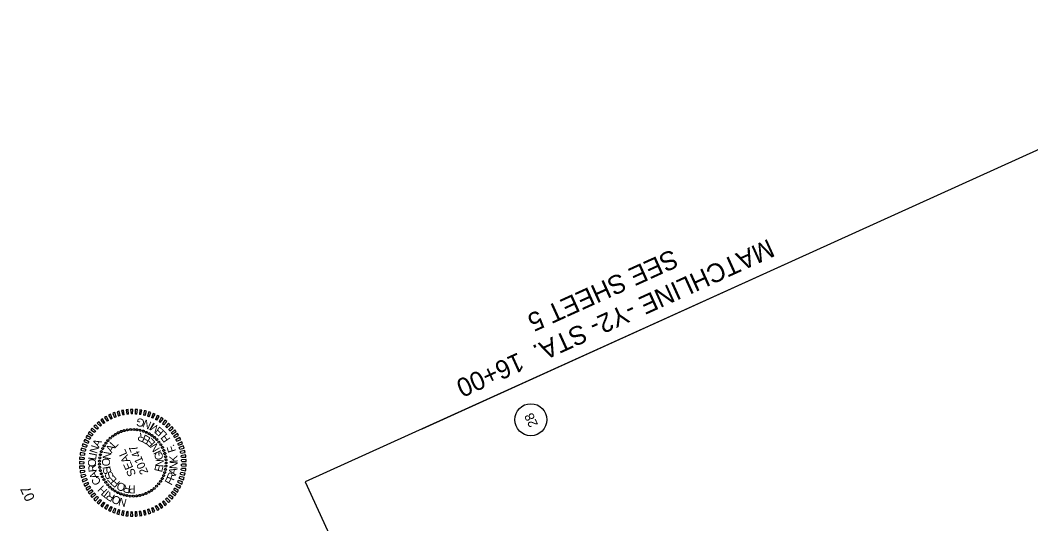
# Model space of a CAD drawing. Extents: x 2048005 to 2049520, y 757591 to 759287.
# Drawn here: x 2048005 to 2048763, y 758824 to 759201 of the extents above; entities that cross this region are included whole.
import ezdxf

# ---------------------------------------------------------------- set-up
doc = ezdxf.new("R2010")
doc.units = 0
for name, color, linetype in [('Default', 7, 'Continuous'), ('Matchline', 7, 'Continuous'), ('Matchline Text', 7, 'Continuous'), ('Sheet Clip Boundary CELL', 7, 'Continuous'), ('Sheet Data Field CELL', 7, 'Continuous'), ('Sheet PE Seal Cell', 7, 'Continuous')]:
    doc.layers.add(name, color=color, linetype=linetype)

msp = doc.modelspace()

# ---------------------------------------------------------------- linework, layer by layer
at = {"layer": 'Default'}
msp.add_line((2048387.91, 758901.83), (2048387.91, 758901.83), dxfattribs=at)
msp.add_circle((2048387.91, 758901.83), 12, dxfattribs=at)
at = {"layer": 'Matchline'}
msp.add_line((2048306.53, 758894.91), (2048583.6, 759020.66), dxfattribs=at)
at = {"layer": 'Sheet Clip Boundary CELL'}
msp.add_lwpolyline([(2048565.47, 757590.62), (2049520.08, 758027.9), (2048982.56, 759201.34), (2048218.78, 758855.25), (2048270.17, 758743.08), (2048168.29, 758696.41), (2048234.11, 758552.71), (2048143.72, 758511.31)], close=True, dxfattribs=at)
at = {"layer": 'Sheet PE Seal Cell'}
for p, q in [((2048068.61, 758899.61), (2048066.86, 758902.47)), ((2048068.36, 758903.46), (2048070.29, 758900.71)), ((2048071.28, 758901.3), (2048069.78, 758904.3)), ((2048071.36, 758905.15), (2048073.04, 758902.25)), ((2048074.08, 758902.75), (2048072.84, 758905.87)), ((2048074.49, 758906.58), (2048075.92, 758903.54)), ((2048076.99, 758903.96), (2048076.03, 758907.17)), ((2048077.73, 758907.74), (2048078.89, 758904.59)), ((2048080, 758904.91), (2048079.32, 758908.19)), ((2048081.06, 758908.61), (2048081.95, 758905.37)), ((2048083.07, 758905.59), (2048082.68, 758908.93)), ((2048084.45, 758909.19), (2048085.06, 758905.89)), ((2048086.2, 758906.02), (2048086.09, 758909.37)), ((2048087.88, 758909.48), (2048088.2, 758906.14)), ((2048089.35, 758906.17), (2048089.53, 758909.52)), ((2048091.32, 758909.48), (2048091.35, 758906.12)), ((2048092.5, 758906.05), (2048092.97, 758909.37)), ((2048094.75, 758909.18), (2048094.49, 758905.83)), ((2048095.63, 758905.66), (2048096.38, 758908.93)), ((2048098.14, 758908.58), (2048097.6, 758905.27)), ((2048098.71, 758905), (2048099.74, 758908.19)), ((2048101.47, 758907.7), (2048100.64, 758904.44)), ((2048101.73, 758904.08), (2048103.03, 758907.17)), ((2048104.7, 758906.53), (2048103.6, 758903.36)), ((2048104.66, 758902.9), (2048106.22, 758905.87)), ((2048107.83, 758905.09), (2048106.46, 758902.03)), ((2048107.47, 758901.48), (2048109.28, 758904.3)), ((2048110.82, 758903.38), (2048109.19, 758900.45)), ((2048110.15, 758899.82), (2048112.2, 758902.48)), ((2048061.62, 758893.27), (2048059.2, 758895.59)), ((2048060.4, 758896.93), (2048062.96, 758894.76)), ((2048063.77, 758895.58), (2048061.55, 758898.1)), ((2048062.86, 758899.33), (2048065.23, 758896.95)), ((2048066.1, 758897.7), (2048064.11, 758900.4)), ((2048065.52, 758901.51), (2048067.68, 758898.94)), ((2048113.65, 758901.43), (2048111.78, 758898.65)), ((2048112.68, 758897.93), (2048114.95, 758900.41)), ((2048116.31, 758899.24), (2048114.2, 758896.63)), ((2048115.04, 758895.84), (2048117.51, 758898.11)), ((2048118.76, 758896.82), (2048116.44, 758894.41)), ((2048117.2, 758893.55), (2048119.86, 758895.6)), ((2048056.48, 758885.36), (2048053.55, 758886.98)), ((2048054.36, 758888.58), (2048057.4, 758887.14)), ((2048057.97, 758888.14), (2048055.18, 758890.01)), ((2048056.13, 758891.53), (2048059.03, 758889.84)), ((2048059.68, 758890.78), (2048057.07, 758892.89)), ((2048058.15, 758894.32), (2048060.89, 758892.38)), ((2048121, 758894.21), (2048118.48, 758892)), ((2048119.17, 758891.08), (2048121.99, 758892.89)), ((2048123.01, 758891.41), (2048120.3, 758889.43)), ((2048120.91, 758888.45), (2048123.88, 758890.02)), ((2048124.77, 758888.46), (2048121.9, 758886.71)), ((2048122.42, 758885.69), (2048125.52, 758886.99)), ((2048054.26, 758879.46), (2048051.09, 758880.56)), ((2048051.62, 758882.27), (2048054.85, 758881.37)), ((2048055.24, 758882.46), (2048052.18, 758883.82)), ((2048052.86, 758885.48), (2048056, 758884.31)), ((2048126.26, 758885.36), (2048123.26, 758883.86)), ((2048123.69, 758882.8), (2048126.89, 758883.83)), ((2048127.49, 758882.14), (2048124.37, 758880.91)), ((2048124.71, 758879.81), (2048127.98, 758880.56)), ((2048049.62, 758872.17), (2048052.98, 758872.13)), ((2048053.08, 758873.27), (2048049.76, 758873.81)), ((2048050, 758875.59), (2048053.33, 758875.26)), ((2048053.53, 758876.39), (2048050.28, 758877.21)), ((2048050.66, 758878.96), (2048053.96, 758878.35)), ((2048128.43, 758878.83), (2048125.22, 758877.88)), ((2048125.46, 758876.75), (2048128.78, 758877.22)), ((2048129.09, 758875.45), (2048125.8, 758874.78)), ((2048125.95, 758873.64), (2048129.3, 758873.82)), ((2048129.45, 758872.03), (2048126.12, 758871.64)), ((2048052.89, 758870.12), (2048049.54, 758870.38)), ((2048049.54, 758868.73), (2048052.89, 758868.97)), ((2048052.97, 758866.97), (2048049.62, 758866.94)), ((2048049.76, 758865.29), (2048053.07, 758865.83)), ((2048089.53, 758869.52), (2048089.53, 758869.52)), ((2048125.79, 758864.2), (2048129.08, 758863.52)), ((2048129.29, 758865.15), (2048125.94, 758865.34)), ((2048126.12, 758867.34), (2048129.45, 758866.94)), ((2048126.17, 758870.49), (2048129.52, 758870.38)), ((2048129.52, 758868.59), (2048126.17, 758868.49)), ((2048053.33, 758863.84), (2048049.99, 758863.51)), ((2048050.27, 758861.89), (2048053.52, 758862.7)), ((2048053.95, 758860.75), (2048050.65, 758860.14)), ((2048051.07, 758858.54), (2048054.24, 758859.63)), ((2048054.83, 758857.72), (2048051.6, 758856.83)), ((2048052.15, 758855.27), (2048055.22, 758856.64)), ((2048124.35, 758858.07), (2048127.47, 758856.83)), ((2048127.96, 758858.41), (2048124.69, 758859.17)), ((2048125.2, 758861.1), (2048128.42, 758860.14)), ((2048128.77, 758861.75), (2048125.45, 758862.23)), ((2048055.98, 758854.78), (2048052.83, 758853.61)), ((2048053.52, 758852.11), (2048056.46, 758853.73)), ((2048057.37, 758851.95), (2048054.33, 758850.52)), ((2048055.15, 758849.08), (2048057.93, 758850.95)), ((2048059, 758849.25), (2048056.1, 758847.56)), ((2048120.27, 758849.56), (2048122.97, 758847.57)), ((2048123.85, 758848.96), (2048120.88, 758850.53)), ((2048121.87, 758852.27), (2048124.73, 758850.52)), ((2048125.49, 758851.99), (2048122.4, 758853.3)), ((2048123.23, 758855.12), (2048126.24, 758853.62)), ((2048126.86, 758855.15), (2048123.67, 758856.18)), ((2048057.03, 758846.2), (2048059.65, 758848.3)), ((2048060.85, 758846.7), (2048058.11, 758844.77)), ((2048059.16, 758843.49), (2048061.58, 758845.81)), ((2048062.92, 758844.32), (2048060.35, 758842.16)), ((2048061.51, 758840.98), (2048063.72, 758843.5)), ((2048065.18, 758842.12), (2048062.81, 758839.75)), ((2048114.15, 758842.37), (2048116.26, 758839.76)), ((2048117.46, 758840.88), (2048114.99, 758843.16)), ((2048116.4, 758844.59), (2048118.72, 758842.16)), ((2048119.82, 758843.39), (2048117.16, 758845.44)), ((2048118.44, 758846.99), (2048120.96, 758844.77)), ((2048121.95, 758846.09), (2048119.13, 758847.91)), ((2048064.06, 758838.68), (2048066.06, 758841.37)), ((2048067.63, 758840.13), (2048065.47, 758837.57)), ((2048066.81, 758836.6), (2048068.56, 758839.46)), ((2048070.24, 758838.36), (2048068.31, 758835.62)), ((2048069.72, 758834.77), (2048071.22, 758837.77)), ((2048072.99, 758836.82), (2048071.3, 758833.92)), ((2048072.78, 758833.19), (2048074.02, 758836.31)), ((2048075.86, 758835.51), (2048074.43, 758832.48)), ((2048075.97, 758831.89), (2048076.93, 758835.1)), ((2048078.83, 758834.46), (2048077.67, 758831.32)), ((2048079.25, 758830.86), (2048079.94, 758834.15)), ((2048099.68, 758830.83), (2048098.66, 758834.02)), ((2048100.58, 758834.57), (2048101.4, 758831.32)), ((2048102.97, 758831.84), (2048101.67, 758834.94)), ((2048103.55, 758835.65), (2048104.64, 758832.48)), ((2048106.16, 758833.14), (2048104.6, 758836.11)), ((2048106.4, 758836.98), (2048107.77, 758833.92)), ((2048109.22, 758834.7), (2048107.42, 758837.53)), ((2048109.14, 758838.55), (2048110.76, 758835.62)), ((2048112.14, 758836.52), (2048110.1, 758839.18)), ((2048111.73, 758840.35), (2048113.6, 758837.57)), ((2048114.9, 758838.59), (2048112.63, 758841.06)), ((2048081.89, 758833.67), (2048080.99, 758830.44)), ((2048082.61, 758830.12), (2048083.01, 758833.45)), ((2048085, 758833.15), (2048084.39, 758829.85)), ((2048086.03, 758829.67), (2048086.14, 758833.03)), ((2048088.14, 758832.89), (2048087.81, 758829.56)), ((2048089.46, 758829.52), (2048089.29, 758832.87)), ((2048091.29, 758832.91), (2048091.26, 758829.56)), ((2048092.9, 758829.66), (2048092.44, 758832.98)), ((2048094.43, 758833.2), (2048094.69, 758829.85)), ((2048096.32, 758830.1), (2048095.57, 758833.37)), ((2048097.54, 758833.75), (2048098.08, 758830.44))]:
    msp.add_line(p, q, dxfattribs=at)
for radius, start, end in [(40, 124.5243, 126.88792), (40, 119.5928, 121.95642), (40, 114.66129, 117.02491), (36.65, 114.94415, 116.74205), (40, 109.72978, 112.0934), (36.65, 110.01265, 111.81054), (40, 104.79828, 107.1619), (36.65, 105.08114, 106.87903), (40, 99.86677, 102.23039), (36.65, 100.14963, 101.94753), (40, 94.93526, 97.29888), (36.65, 95.21813, 97.01602), (40, 90.00376, 92.36738), (36.65, 90.28662, 92.08451), (40, 85.07225, 87.43587), (36.65, 85.35511, 87.15301), (36.65, 80.4236, 82.2215), (40, 80.14074, 82.50436), (36.65, 75.4921, 77.28999), (40, 75.20924, 77.57285), (36.65, 70.56059, 72.35849), (40, 70.27773, 72.64135), (36.65, 65.62908, 67.42698), (40, 65.34622, 67.70984), (40, 60.41472, 62.77833), (40, 55.48321, 57.84683), (40, 139.31883, 141.68244), (40, 134.38732, 136.75094), (40, 129.45581, 131.81943), (36.65, 134.67018, 136.46808), (36.65, 129.73867, 131.53657), (36.65, 124.80717, 126.60506), (36.65, 119.87566, 121.67355), (36.65, 60.69758, 62.49547), (36.65, 55.76607, 57.56397), (36.65, 50.83456, 52.63246), (40, 50.5517, 52.91532), (36.65, 45.90306, 47.70095), (40, 45.6202, 47.98381), (40, 40.68869, 43.05231), (40, 154.11335, 156.47696), (40, 149.18184, 151.54546), (40, 144.25033, 146.61395), (36.65, 149.4647, 151.2626), (36.65, 144.53319, 146.33109), (36.65, 139.60169, 141.39958), (36.65, 40.97155, 42.76944), (36.65, 36.04004, 37.83794), (36.65, 31.10854, 32.90643), (40, 35.75718, 38.1208), (40, 30.82567, 33.18929), (40, 25.89417, 28.25779), (40, 163.97636, 166.33998), (40, 159.04485, 161.40847), (36.65, 164.25922, 166.05712), (36.65, 159.32771, 161.12561), (36.65, 154.39621, 156.1941), (36.65, 26.17703, 27.97492), (36.65, 21.24552, 23.04342), (36.65, 16.31402, 18.11191), (40, 20.96266, 23.32628), (40, 16.03115, 18.39477), (40, 173.83937, 176.20299), (40, 168.90787, 171.27148), (36.65, 174.12223, 175.92013), (36.65, 169.19073, 170.98862), (36.65, 11.38251, 13.1804), (36.65, 6.451, 8.2489), (40, 11.09965, 13.46327), (40, 6.16814, 8.53176), (40, 1.23663, 3.60025), (40, 178.77088, 181.1345), (40, 183.70239, 186.06601), (36.65, 179.05374, 180.85164), (36.65, 183.98525, 185.78314), (36.65, 351.65648, 353.45438), (36.65, 1.5195, 3.31739), (36.65, 356.58799, 358.38588), (40, 351.37362, 353.73724), (40, 356.30513, 358.66875), (40, 188.63389, 190.99751), (40, 193.5654, 195.92902), (40, 198.49691, 200.86053), (36.65, 188.91676, 190.71465), (36.65, 193.84826, 195.64616), (36.65, 198.77977, 200.57766), (36.65, 341.79347, 343.59136), (36.65, 346.72497, 348.52287), (40, 341.51061, 343.87422), (40, 346.44211, 348.80573), (40, 203.42841, 205.79203), (40, 208.35992, 210.72354), (36.65, 203.71128, 205.50917), (36.65, 208.64278, 210.44068), (36.65, 213.57429, 215.37218), (36.65, 326.99895, 328.79684), (36.65, 331.93045, 333.72835), (36.65, 336.86196, 338.65986), (40, 331.64759, 334.01121), (40, 336.5791, 338.94272), (40, 213.29143, 215.65505), (40, 218.22293, 220.58655), (40, 223.15444, 225.51806), (36.65, 218.5058, 220.30369), (36.65, 223.4373, 225.2352), (36.65, 228.36881, 230.16671), (36.65, 312.20443, 314.00232), (36.65, 317.13593, 318.93383), (36.65, 322.06744, 323.86534), (40, 316.85307, 319.21669), (40, 321.78458, 324.1482), (40, 326.71609, 329.0797), (40, 228.08595, 230.44957), (40, 233.01746, 235.38107), (36.65, 233.30032, 235.09821), (40, 237.94896, 240.31258), (36.65, 238.23182, 240.02972), (40, 242.88047, 245.24409), (36.65, 243.16333, 244.96123), (36.65, 248.09484, 249.89273), (36.65, 253.02634, 254.82424), (36.65, 282.61539, 284.41328), (36.65, 287.54689, 289.34479), (36.65, 292.4784, 294.27629), (36.65, 297.40991, 299.2078), (40, 297.12704, 299.49066), (36.65, 302.34141, 304.13931), (40, 302.05855, 304.42217), (36.65, 307.27292, 309.07081), (40, 306.99006, 309.35368), (40, 311.92156, 314.28518), (40, 247.81198, 250.17559), (40, 252.74348, 255.1071), (40, 257.67499, 260.03861), (36.65, 257.95785, 259.75575), (40, 262.6065, 264.97011), (36.65, 262.88936, 264.68725), (40, 267.538, 269.90162), (36.65, 267.82087, 269.61876), (40, 272.46951, 274.83313), (36.65, 272.75237, 274.55027), (36.65, 277.68388, 279.48177), (40, 277.40102, 279.76464), (40, 282.33252, 284.69614), (40, 287.26403, 289.62765), (40, 292.19554, 294.55916)]:
    msp.add_arc((2048089.53, 758869.52), radius, start, end, dxfattribs=at)
for centre, major_axis in [((2048083.1, 758893.68), (-0.241, 0.702)), ((2048085.46, 758894.18), (-0.172, 0.722)), ((2048087.86, 758894.46), (-0.101, 0.735)), ((2048090.27, 758894.51), (-0.03, 0.742)), ((2048092.68, 758894.32), (0.042, 0.741)), ((2048095.06, 758893.9), (0.113, 0.734)), ((2048070.91, 758886.2), (-0.586, 0.456)), ((2048072.61, 758887.92), (-0.539, 0.51)), ((2048074.46, 758889.47), (-0.488, 0.56)), ((2048076.46, 758890.83), (-0.431, 0.604)), ((2048078.58, 758891.99), (-0.371, 0.643)), ((2048080.8, 758892.94), (-0.307, 0.676)), ((2048097.39, 758893.25), (0.184, 0.719)), ((2048099.64, 758892.38), (0.252, 0.698)), ((2048101.8, 758891.3), (0.318, 0.671)), ((2048103.85, 758890.01), (0.382, 0.637)), ((2048105.76, 758888.54), (0.441, 0.597)), ((2048107.52, 758886.88), (0.497, 0.552)), ((2048066.92, 758880.18), (-0.692, 0.269)), ((2048068.05, 758882.31), (-0.663, 0.334)), ((2048069.39, 758884.32), (-0.627, 0.397)), ((2048109.11, 758885.07), (0.548, 0.501)), ((2048110.52, 758883.1), (0.593, 0.446)), ((2048111.73, 758881.02), (0.634, 0.387)), ((2048112.74, 758878.82), (0.668, 0.324)), ((2048064.81, 758873.27), (-0.74, 0.06)), ((2048065.29, 758875.63), (-0.731, 0.131)), ((2048066, 758877.94), (-0.715, 0.201)), ((2048113.53, 758876.54), (0.696, 0.258)), ((2048114.09, 758874.19), (0.718, 0.189)), ((2048114.43, 758871.8), (0.733, 0.119)), ((2048064.56, 758868.45), (-0.738, -0.083)), ((2048064.57, 758870.86), (-0.742, -0.012)), ((2048064.78, 758866.04), (-0.726, -0.154)), ((2048065.23, 758863.67), (-0.708, -0.224)), ((2048114.04, 758864.58), (0.736, -0.095)), ((2048114.4, 758866.97), (0.742, -0.024)), ((2048114.53, 758869.38), (0.741, 0.048)), ((2048065.9, 758861.35), (-0.683, -0.291)), ((2048066.8, 758859.11), (-0.652, -0.355)), ((2048067.91, 758856.96), (-0.614, -0.417)), ((2048111.61, 758857.78), (0.678, -0.302)), ((2048112.64, 758859.96), (0.704, -0.235)), ((2048113.45, 758862.24), (0.724, -0.166)), ((2048069.23, 758854.93), (-0.571, -0.474)), ((2048070.73, 758853.04), (-0.523, -0.527)), ((2048072.41, 758851.3), (-0.47, -0.575)), ((2048074.25, 758849.74), (-0.412, -0.618)), ((2048076.23, 758848.35), (-0.35, -0.654)), ((2048103.62, 758848.87), (0.46, -0.583)), ((2048105.55, 758850.32), (0.514, -0.535)), ((2048107.33, 758851.96), (0.563, -0.483)), ((2048108.94, 758853.76), (0.607, -0.427)), ((2048110.37, 758855.7), (0.646, -0.366)), ((2048078.33, 758847.17), (-0.286, -0.685)), ((2048080.54, 758846.19), (-0.218, -0.71)), ((2048082.83, 758845.43), (-0.149, -0.727)), ((2048085.19, 758844.9), (-0.078, -0.738)), ((2048087.59, 758844.59), (-0.006, -0.742)), ((2048090, 758844.52), (0.066, -0.739)), ((2048092.41, 758844.68), (0.137, -0.73)), ((2048094.79, 758845.08), (0.206, -0.713)), ((2048097.13, 758845.7), (0.274, -0.69)), ((2048099.39, 758846.54), (0.34, -0.66)), ((2048101.56, 758847.6), (0.402, -0.624))]:
    msp.add_ellipse(centre, major_axis=major_axis, ratio=0.999708, dxfattribs=at)

# ---------------------------------------------------------------- texts
at = {"layer": 'Default'}
msp.add_text('28', height=7, rotation=114.61022, dxfattribs=at).set_placement((2048393.42, 758898.2))
at = {"layer": 'Matchline Text'}
for s, p in [('MATCHLINE -Y2- STA.  16+00', (2048566.12, 759037.71)), ('SEE SHEET 5', (2048494.04, 759029.98))]:
    msp.add_text(s, height=14, rotation=204.41156, dxfattribs=at).set_placement(p)
at = {"layer": 'Sheet Data Field CELL'}
msp.add_text('07', height=7.5, rotation=114.57389, dxfattribs=at).set_placement((2048016.4, 758842.85))
at = {"layer": 'Sheet PE Seal Cell'}
for s, height, rotation, p in [('G', 6, 166.05817, (2048098.91, 758901.82)), ('N', 6, 156.72193, (2048104, 758899.88)), ('I', 6, 150.36644, (2048106.1, 758898.76)), ('M', 6, 145.42022, (2048110.51, 758895.89)), ('E', 6, 136.77789, (2048113.49, 758893.14)), ('R', 6, 157.60789, (2048099.92, 758890.11)), ('E', 6, 148.85489, (2048103.41, 758887.97)), ('E', 6, 132.45124, (2048106.89, 758884.6)), ('L', 6, 130.6615, (2048115.83, 758890.5)), ('F', 6, 124.62183, (2048118.04, 758887.4)), ('N', 6, 72.21724, (2048062.6, 758876)), ('A', 6, 63.28691, (2048064.24, 758880.69)), ('A', 6, 57.83195, (2048073.85, 758876.49)), ('L', 6, 47.69888, (2048076.14, 758880.06)), ('SEAL', 6.184, 113.61022, (2048092.18, 758860.87)), ('20147', 6.185, 113.61022, (2048101.29, 758862.3)), ('N', 6, 121.60204, (2048110.14, 758879.91)), ('F', 6, 106.8043, (2048122, 758878.28)), ('.', 6, 105.16865, (2048120.79, 758881.66)), ('O', 6, 89.24164, (2048061.9, 758866.4)), ('L', 6, 82.04135, (2048061.9, 758871.24)), ('I', 6, 78.05369, (2048062.31, 758874.29)), ('O', 6, 92.06578, (2048072.61, 758867.03)), ('N', 6, 80.35233, (2048072.68, 758871.64)), ('I', 6, 114.15248, (2048111.1, 758877.57)), ('G', 6, 98.56782, (2048112.4, 758871.96)), ('K', 6, 93.64119, (2048123.2, 758869.89)), ('R', 6, 96.53088, (2048062.56, 758862.9)), ('I', 6, 100.45566, (2048073.01, 758865.39)), ('S', 6, 114.61559, (2048074.1, 758862.5)), ('E', 6, 76.18456, (2048111.37, 758862.08)), ('N', 6, 86.03809, (2048112.36, 758866.19)), ('A', 6, 76.02706, (2048121.79, 758859.91)), ('N', 6, 85.2668, (2048122.86, 758864.61)), ('A', 6, 112.01811, (2048064.06, 758858.94)), ('C', 6, 120.9025, (2048066.13, 758854.88)), ('S', 6, 122.99577, (2048075.76, 758859.52)), ('E', 6, 131.79489, (2048077.97, 758856.95)), ('F', 6, 61.37169, (2048118.43, 758852.28)), ('R', 6, 68.57911, (2048120.25, 758855.76)), ('H', 6, 135.27137, (2048070.99, 758849.02)), ('F', 6, 140.0221, (2048080.49, 758854.96)), ('O', 6, 158.96977, (2048084.69, 758853.18)), ('R', 6, 170.89606, (2048088.33, 758852.49)), ('P', 6, 179.40332, (2048091.62, 758852.52)), ('T', 6, 141.66452, (2048073.4, 758847.06)), ('R', 6, 148.76145, (2048076.7, 758845)), ('O', 6, 156.42405, (2048081.11, 758843.07)), ('N', 6, 165.44384, (2048085.4, 758842.07))]:
    msp.add_text(s, height=height, rotation=rotation, dxfattribs=at).set_placement(p)

doc.saveas('drawing.dxf')
